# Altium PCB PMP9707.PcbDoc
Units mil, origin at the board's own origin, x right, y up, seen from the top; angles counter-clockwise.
Board outline 2100 x 1500 mil, 2 copper layers (Top Layer, Bottom Layer), stack 62 mil thick; 31 components, 15 nets, 63 pads, 0 vias.
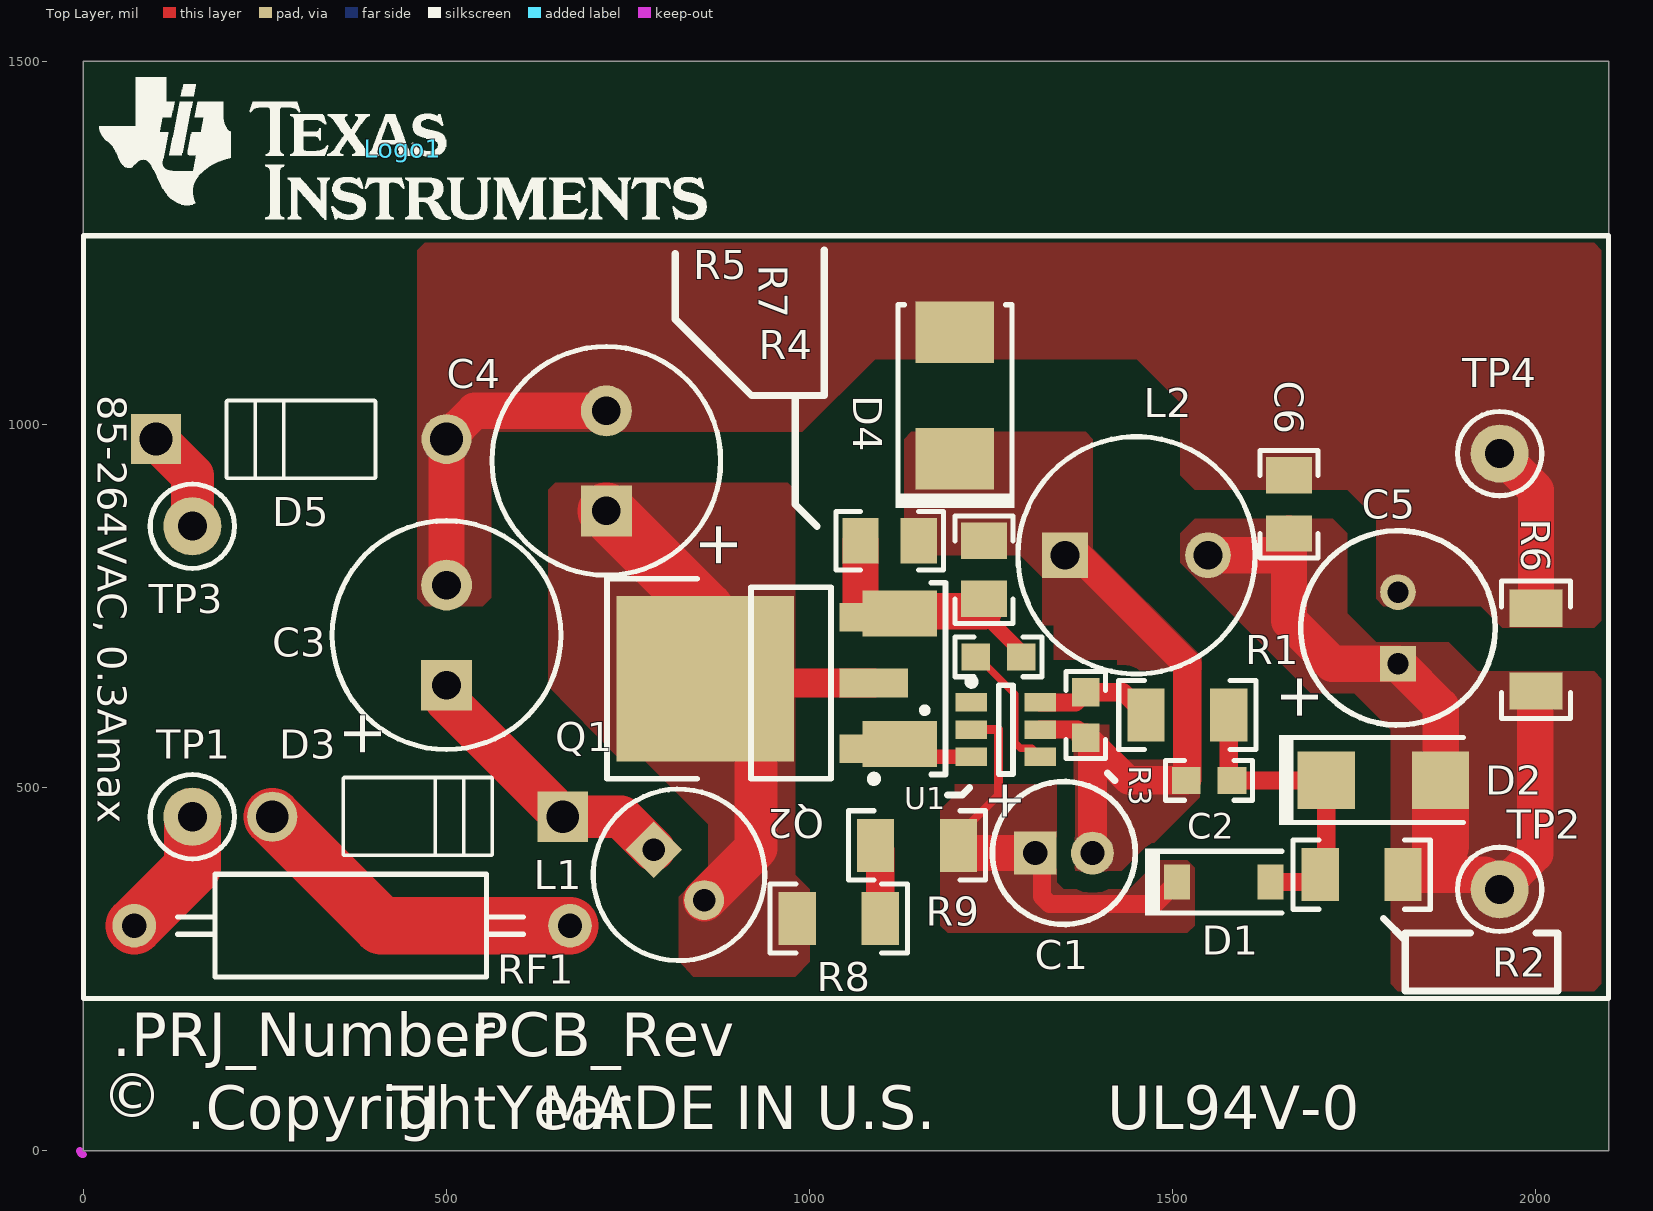
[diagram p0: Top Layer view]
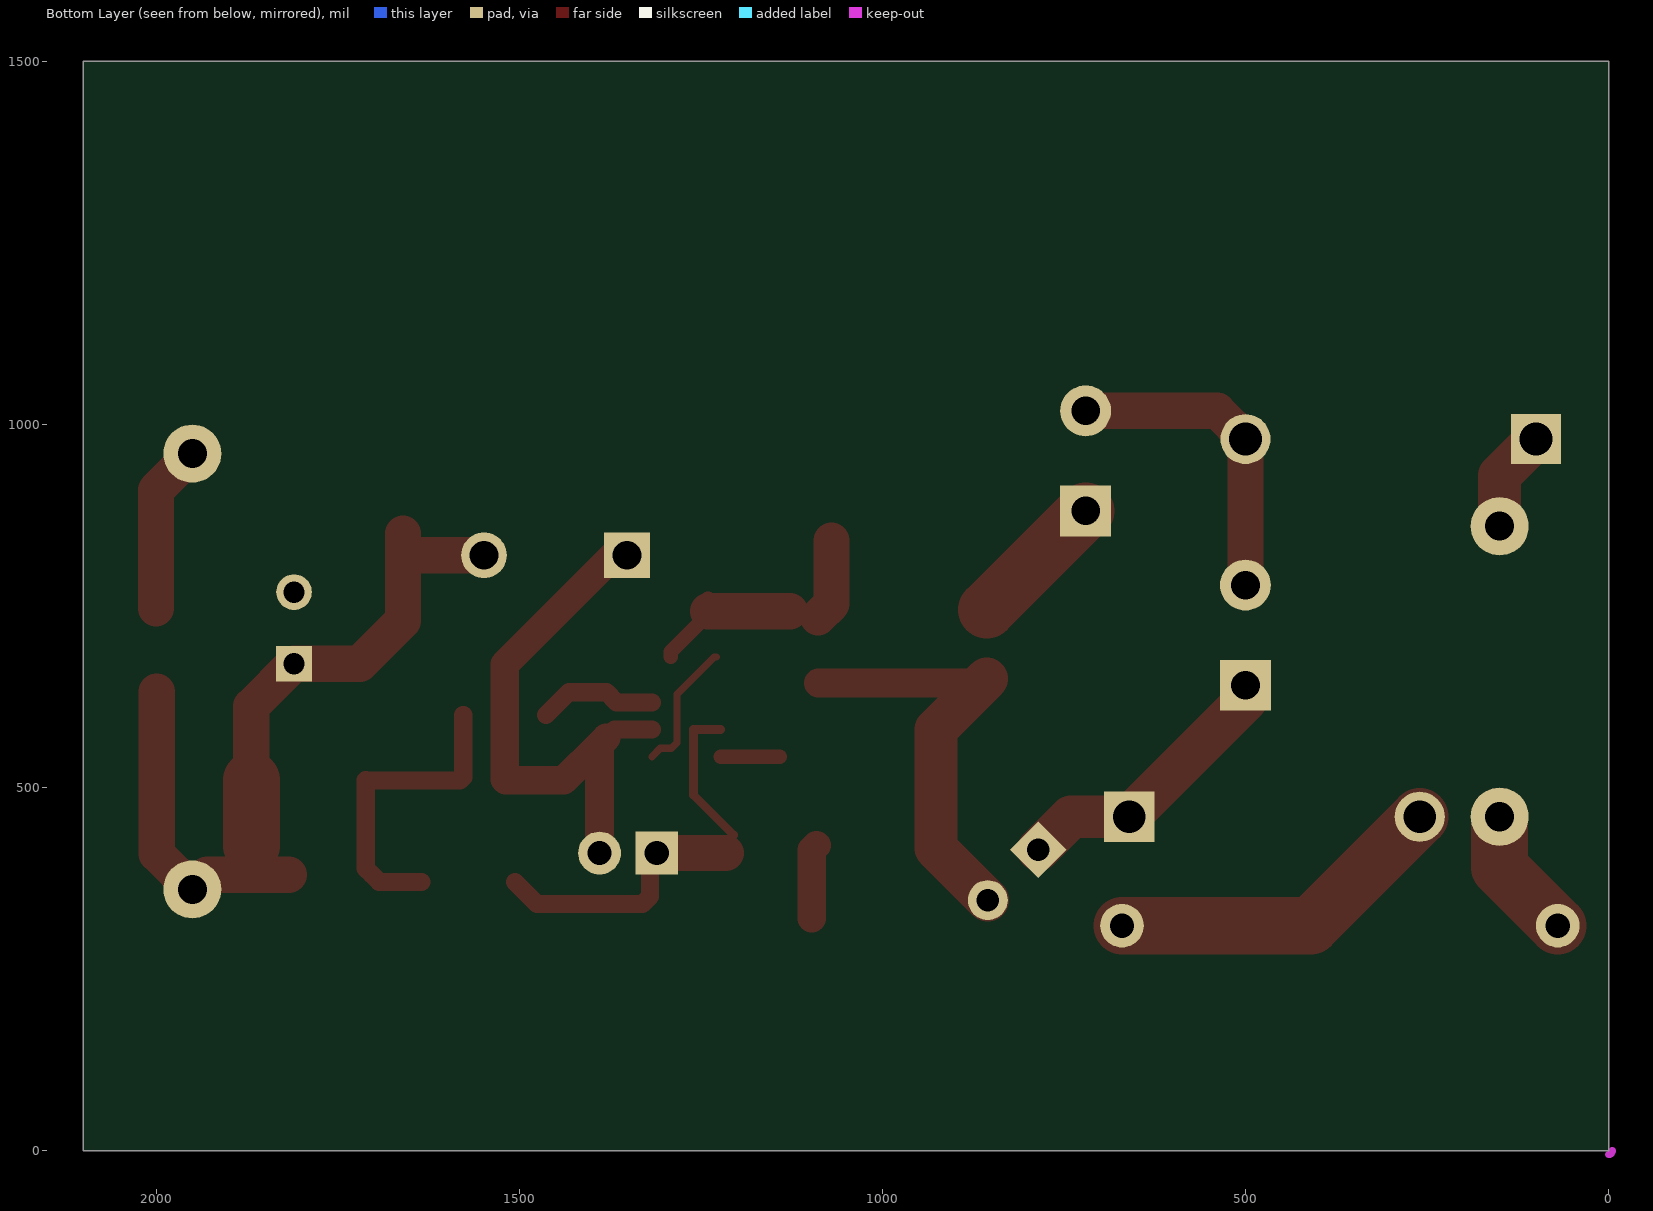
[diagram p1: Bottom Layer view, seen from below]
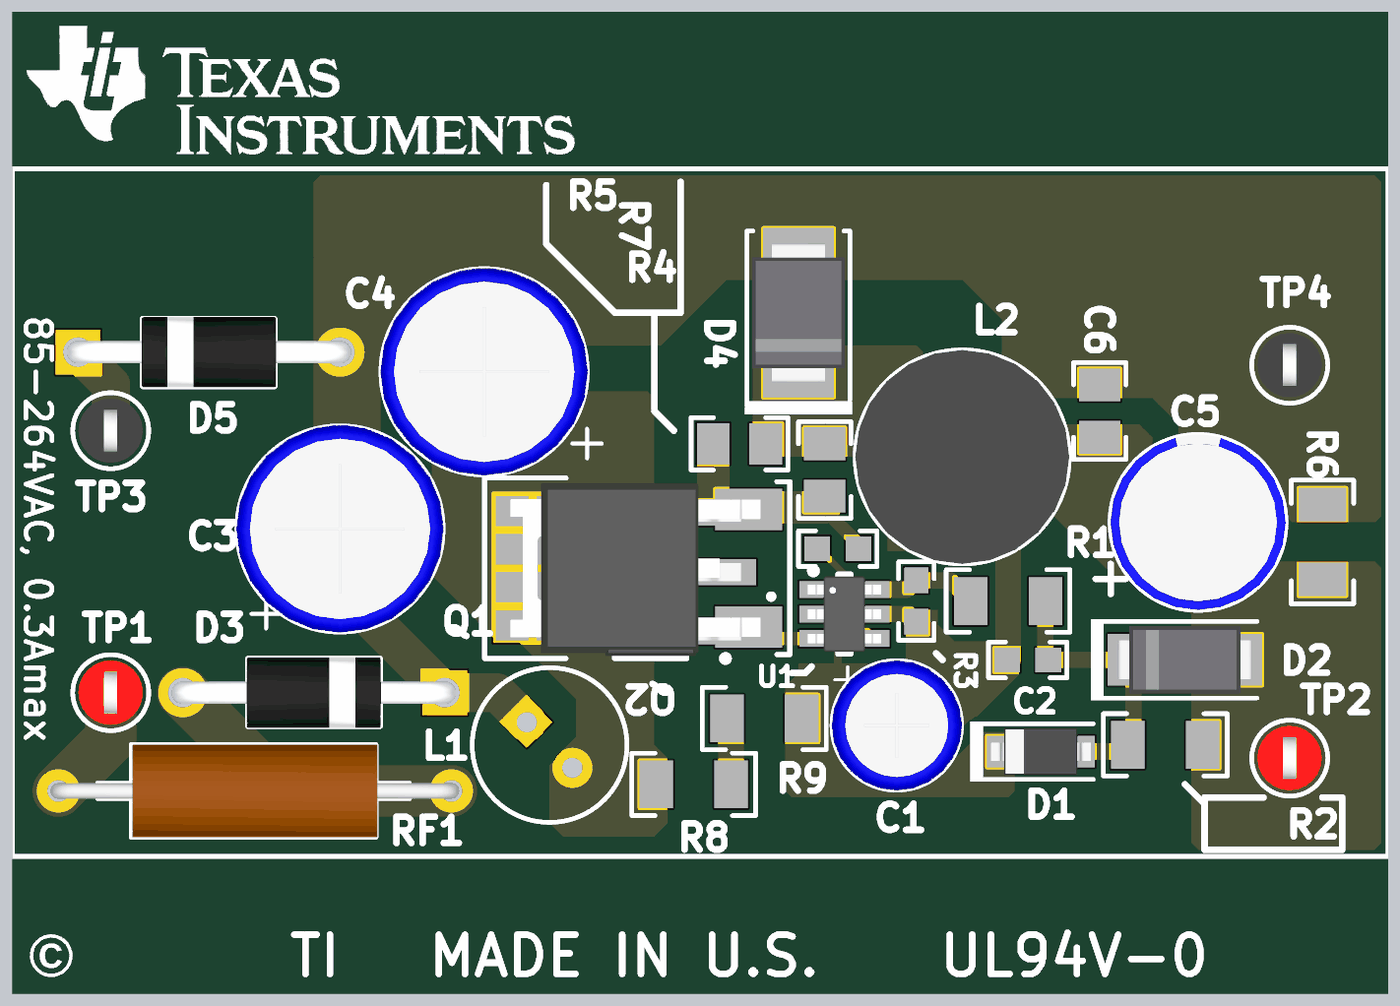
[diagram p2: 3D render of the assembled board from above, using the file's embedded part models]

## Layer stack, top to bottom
Top Layer: signal copper 1.4
Dielectric: core 59.2, FR-4, Dk 4.8
Bottom Layer: signal copper 1.4

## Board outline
0,0 2100,0 2100,1500 0,1500

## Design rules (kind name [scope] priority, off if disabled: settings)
AcuteAngle [All] p1: minimum=4.50000000000000E+0001 checktracksonly=FALSE
AssemblyTestPointUsage [All] p1: valid=2
Clearance Clearance_BoardEdge_MountingHoles [OnCopper and InComponentClass('Mounting Holes') vs IsKeepOut] p1: gap=40
Clearance Clearance_BoardEdge_Poly [OnCopper and InPoly vs IsKeepOut] p2: gap=25
Clearance Clearance_BoardEdge [OnCopper and Not InComponentClass('Logo') and not InComponentClass('FiducialMark') and not InRegion(1000,500,4000,800) and Not IsKeepout vs IsKeepOut] p3: gap=75
Clearance Clearance_Poly [InPolygon] p4: gap=25
Clearance [All] p5: gap=8
ComponentClearance ComponentClearance_Logo [InComponentClass(Logo)] p1: gap=50 collisioncheckmode=3 verticalgap=10 showdistances=FALSE
ComponentClearance ComponentClearance_ScrewToNut [(HasFootprint('NY PMS 440 0025 PH')) vs (HasFootprint('Keystone_1902C'))] p2: gap=5 collisioncheckmode=3 verticalgap=10 showdistances=FALSE
ComponentClearance ComponentClearance_MountingHoles [InComponentClass('Mounting Holes')] p3: gap=2 collisioncheckmode=3 verticalgap=100000 showdistances=FALSE
ComponentClearance ComponentClearance_SmallPassives [HasFootprint('0201*') or HasFootprint('0402*') or HasFootprint('0508') or HasFootprint('0603*') or HasFootprint('0612') or HasFootprint('0805*') or HasFootprint('0815*') or HasFootprint('0830*') or HasFootprint('1206*') or HasFootprint('1210*') or HasFootprint('1808*') or HasFootprint('1812*') or HasFootprint('1825*') or HasFootprint('2010*') or HasFootprint('2220*') or HasFootprint('2225*') or HasFootprint('2512*') or HasFootprint('2728*') or HasFootprint('3518*') vs HasFootprint('0201*') or HasFootprint('0402*') or HasFootprint('0508') or HasFootprint('0603*') or HasFootprint('0612') or HasFootprint('0805*') or HasFootprint('0815*') or HasFootprint('0830*') or HasFootprint('1206*') or HasFootprint('1210*') or HasFootprint('1808*') or HasFootprint('1812*') or HasFootprint('1825*') or HasFootprint('2010*') or HasFootprint('2220*') or HasFootprint('2225*') or HasFootprint('2512*') or HasFootprint('2728*') or HasFootprint('3518*')] p4: gap=10 collisioncheckmode=3 verticalgap=10 showdistances=FALSE
ComponentClearance ComponentClearance_THtoSMT [IsThruComponent vs IsSMTComponent] p5: gap=10 collisioncheckmode=3 verticalgap=10 showdistances=FALSE
ComponentClearance ComponentClearance_THtoTH [IsThruComponent vs IsThruComponent] p6: gap=10 collisioncheckmode=3 verticalgap=10 showdistances=FALSE
ComponentClearance [All] p7: gap=10 collisioncheckmode=3 verticalgap=10 showdistances=FALSE
DiffPairsRouting [All] p1: maxlimit=100 minlimit=10 mostfreqgap=10 maxuncoupledlength=1000
FabricationTestPointUsage TestPointUsage [All] p1: valid=2 allowmultiple=FALSE
FabricationTestpoint Testpoint [All] p1: side=3 testpointundercomponent=TRUE minsize=40 maxsize=100 preferedsize=60 minholesize=0 maxholesize=40 preferedholesize=32 testpointgrid=1 allowsidetop=TRUE allowsidebottom=TRUE usegrid=TRUE gridtolerance=0.01
FanoutControl Fanout_LCC [IsLCC] p1: bgadir=Out bgaviamode=Centered fanoutstyle=Auto fanoutdirection=Alternating viagrid=1 // Fanout_LCC (Default Rule)
FanoutControl Fanout_BGA [IsBGA] p2: bgadir=Out bgaviamode=Centered fanoutstyle=Auto fanoutdirection=Alternating viagrid=1 // Fanout_BGA (Default Rule)
FanoutControl Fanout_Default [All] p4: bgadir=Out bgaviamode=Centered fanoutstyle=Auto fanoutdirection=Alternating viagrid=1 // Fanout_Default (Default Rule)
FanoutControl Fanout_Small [(CompPinCount < 5)] p5: bgadir=Out bgaviamode=Centered fanoutstyle=Auto fanoutdirection=OutThenIn viagrid=1 // Fanout_Small (Default Rule)
HoleSize [All] p1: absolutevalues=TRUE maxlimit=251 minlimit=8 maxpercent=80.000 minpercent=20.000
MinimumAnnularRing [All] p1: minimumring=9
MinimumSolderMaskSliver MinimumSolderMaskSliver_Logo [InComponentClass('Logo') vs InComponentClass('Logo')] p1: minsoldermaskwidth=0.7
MinimumSolderMaskSliver [All] p2: minsoldermaskwidth=4
PlaneConnect [All] p1: planeconnectstyle=Relief reliefexpansion=10 reliefentries=4 reliefconductorwidth=10 reliefairgap=10
PolygonConnect PolygonConnect_6 [All vs IsNamedPolygon('GND_T') Or  IsNamedPolygon('C5_1_T') Or  IsNamedPolygon('C1_2_T') Or  IsNamedPolygon('C1_1_T') Or  IsNamedPolygon('C4_1')] p1: connectstyle=Direct reliefconductorwidth=10 reliefentries=4 polygonreliefangle="90 Angle" airgapwidth=10
PolygonConnect PolygonConnect_5 [All vs IsNamedPolygon('C4_1') Or  IsNamedPolygon('C5_1_T')] p2: connectstyle=Direct reliefconductorwidth=10 reliefentries=4 polygonreliefangle="90 Angle" airgapwidth=10
PolygonConnect PolygonConnect_4 [All vs IsNamedPolygon('C1_2') Or  IsNamedPolygon('C4_1') Or  IsNamedPolygon('C5_1') Or  IsNamedPolygon('GND')] p3: connectstyle=Direct reliefconductorwidth=10 reliefentries=4 polygonreliefangle="90 Angle" airgapwidth=10
PolygonConnect PolygonConnect_3 [All vs IsNamedPolygon('C4_1') Or  IsNamedPolygon('GND') Or  IsNamedPolygon('C5_1')] p4: connectstyle=Direct reliefconductorwidth=10 reliefentries=4 polygonreliefangle="90 Angle" airgapwidth=10
PolygonConnect PolygonConnect_2 [All vs IsNamedPolygon('C5_1')] p5: connectstyle=Direct reliefconductorwidth=10 reliefentries=4 polygonreliefangle="90 Angle" airgapwidth=10
PolygonConnect PolygonConnect_1 [All vs IsNamedPolygon('C1_2_T') Or  IsNamedPolygon('C4_1_T') Or  IsNamedPolygon('GND_T')] p6: connectstyle=Direct reliefconductorwidth=10 reliefentries=4 polygonreliefangle="90 Angle" airgapwidth=10
PolygonConnect [All] p7: connectstyle=Relief reliefconductorwidth=10 reliefentries=4 polygonreliefangle="90 Angle" airgapwidth=10
RoutingVias [All] p1: holewidth=16 width=34 viastyle="Through Hole" minholewidth=8 minwidth=26 maxholewidth=40 maxwidth=65
SMDToCorner [All] p1: distance=30000
SilkToSilkClearance [All] p1: silktosilkclearance=5
SilkscreenOverComponentPads [All] p1: minsilkscreentomaskgap=5
SolderMaskExpansion [All] p1: expansion=3
Width [All] p1: maxlimit=100 minlimit=6 preferedwidth=10 checkconnectedcopper=TRUE
14 further rules are at their usual default settings.

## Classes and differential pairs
component class Logo: Logo1

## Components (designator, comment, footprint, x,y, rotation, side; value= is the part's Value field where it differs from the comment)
C1 "UVR1V100MDD1TA" CAPPR2-5x11 1350,410 r0 top
C2 "06035A220JAT2A" 0603 1550,510 r180 top
C3 "400AX6R8M8x11" CAPPRD350W60D800H1100 500,710 r90 top
C4 "400AX6R8M8x11" CAPPRD350W60D800H1100 720,950 r90 top
C5 "EEU-FR1E151B" CAPPR250W50D630H1120 1810,720 r90 top
C6 "08055C105KAT2A" 0805_HV 1660,890 r90 top
D1 "1N4148W-7-F" SOD-123 1570,370 r0 top
D2 "ES1J-TP" SMA 1790,510.32 r0 top
D3 "1N4007" DO-41 460,460 r180 top
D4 "MURS160-13-F" SMB 1200,1040 r90 top
D5 "1N4007" DO-41 300,980 r0 top
L1 "7447462102" IND_WE-TI_XS 820,380 r315 top
L2 "744772221" IND_WE-TI_8095 1450,820 r0 top
Logo1 "Texas Instruments" TI_Stacked_Overlay_Small 440,1380 r0 top
Q1 "FJD5304DTF" DPAK 990,650 r180 top
Q2 "STN2580" SOT-223 974.25,644.09 r180 top
R1 "CRCW120638K3FKEA" 1206 1520,600 r0 top
R2 "CRCW1206475KFKEA" 1206 1760,380.32 r180 top
R3 "CRCW060317K8FKEA" 0603 1380,600 r90 top
R4 "CRCW0603511RFKEA" 0603 1260,680 r180 top
R5 "CRCW08051R20JNEA" 0805_HV 1110,840 r0 top
R6 "CRCW120612K0JNEA" 1206 2000,690 r270 top
R7 "CRCW08051R20JNEA" 0805_HV 1240,800 r90 top
R8 "CRCW12063M30JNEA" 1206 1040,320 r0 top
R9 "CRCW12063M30JNEA" 1206 1147.75,420.61 r0 top
RF1 "FKN1WSJR-52-4R7" RESAD1524W55L900D150 370,310 r180 top
TP1 "5000" Keystone5000 150,460 r0 top
TP2 "5000" Keystone5000 1950,360 r0 top
TP3 "5001" Keystone5001 150,860 r0 top
TP4 "5001" Keystone5001 1950,960 r0 top
U1 "UCC28722DBV" DBV0006A_N 1270,580 r0 top

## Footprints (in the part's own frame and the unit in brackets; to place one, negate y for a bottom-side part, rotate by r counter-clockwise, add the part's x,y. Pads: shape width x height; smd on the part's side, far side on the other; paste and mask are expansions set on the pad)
0603 [mm] "0603 from SM-752 data"
  rect 1x0.95 smd: 1(-0.8,0) 2(0.8,0)
  silkscreen extent -1.52,-0.69 1.52,0.69, body extent -0.87,-0.47 0.87,0.47, height 0.85
0805_HV [mil] "0805 with 30mil clearance between pads"
  rect 50x63 smd: 1(-40,0) 2(40,0)
  silkscreen extent -74,-40 74,40, body extent -43,-29 43,29, height 43
1206 [mm] "1206 from SM-752 data"
  rect 1.3x1.85 smd: 1(-1.45,0) 2(1.45,0)
  silkscreen extent -2.4,-1.21 2.4,1.21, body extent -1.7,-0.9 1.7,0.9, height 1.35
CAPPR2-5x11 [mm] "Capacitor, Electrolytic, Radial; Body 5 x 11 mm (Dia.xH typ); Pin Spacing 2 mm (typ)"
  rect 1.5x1.5 hole 0.85: 1(-1,0)
  round 1.5 hole 0.85: 2(1,0)
  silkscreen extent -2.5,-2.5 2.5,2.5, body extent -2.53,-2.53 2.53,2.52, height 11.29
CAPPR250W50D630H1120 [mm] "PANASONIC"
  rect 1.25x1.25 hole 0.75: 1(-1.25,0)
  round 1.25 hole 0.75: 2(1.25,0)
  silkscreen extent -3.4,-3.4 3.4,3.4, body extent -3.37,-3.39 3.4,3.39, height 12.21
CAPPRD350W60D800H1100 [mm] "Capacitor, Alum, 8x11mm"
  rect 1.78x1.78 hole 1: 1(-1.75,0)
  round 1.78 hole 1: 2(1.75,0)
  silkscreen extent -4,-4 4,4, body extent -4.03,-4.03 4.03,4.02, height 11.79
DBV0006A_N [mm] "SOT23, 6-Leads, Body 2.9x1.6mm, Pitch 0.95mm, Lead Span 2.8mm, IPC Medium Density"
  rect 1.1x0.65 smd: 1(-1.2,0.95) 2(-1.2,0) 3(-1.2,-0.95) 4(1.2,-0.95) 5(1.2,0) 6(1.2,0.95)
  silkscreen extent -1.32,-1.55 0.25,1.8, body extent -1.42,-1.46 1.42,1.46, height 1.11
DO-41 [mm] "diode"
  rect 1.75x1.75 hole 1.15: 1(-5.08,0)
  round 1.75 hole 1.15: 2(5.08,0)
  silkscreen extent -2.62,-1.37 2.59,1.35, body extent -5.51,-1.36 5.51,1.36, height 2.72
DPAK [mm] "D-PAK, 3-Pads, Body 6.22x6.73mm (max), TO-252AA using nominal STEP model"
  rect 2.6x1.6 smd: 1(-3.4,2.28) 3(-3.4,-2.28)
  rect 6.2x5.8 smd paste-2.9: 4(3.4,0)
  silkscreen extent -5,-3.5 6.83,3.5, body extent -3.86,-3.29 5.84,3.29, height 2.48
IND_WE-TI_8095 [mm] "Wurth WE-TI 8095"
  rect 1.6x1.6 hole 1: 1(-2.5,0)
  round 1.6 hole 1: 2(2.5,0)
  silkscreen extent -4.15,-4.15 4.15,4.15, body extent -4.12,-4.14 4.15,4.14, height 10
IND_WE-TI_XS [mm] "Wurth WE-TI 5075"
  rect 1.4x1.4 hole 0.787: 1(-1.25,0)
  round 1.4 hole 0.787: 2(1.25,0)
  silkscreen extent -3,-3 3,3, body extent -3.01,-3.01 3.01,3.01, height 8.5
Keystone5000 [mil] "For Keystone 500x miniature loop terminals"
  round 80 hole 40: 1(0,0)
  silkscreen extent -58,-58 58,58, body extent -49,-49 49,49, height 182
Keystone5001 [mil] "For Keystone 500x miniature loop terminals"
  round 80 hole 40: 1(0,0)
  silkscreen extent -58,-58 58,58, body extent -49,-49 49,49, height 182
RESAD1524W55L900D150 [mil]
  round 60 hole 33.46: 1(-300,0) 2(300,0)
  silkscreen extent -236,-71 240,71, body extent -312,-71 312,71, height 141
SMA [mm] "Molded Diode, 2-Leads, Body 4.3x2.6mm, IPC Medium Density, based on OnSemi component dimensions and land pattern"
  rect 2x2 smd: 1(-2,0) 2(2,0)
  silkscreen extent -3.66,-1.57 2.79,1.57, body extent -2.6,-1.3 2.6,1.3, height 2.42
SMB [mil] "Molded Diode, 2-Leads, Body 5.4x3.6mm, IPC Medium Density, based on OnSemi component dimensions"
  rect 85x107.99 smd: 1(-87.01,0) 2(87.01,0)
  silkscreen extent -155,-82 125,82, body extent -106,-71 106,71, height 91
SOD-123 [mm] "On Semi recommended land pattern"
  rect 0.915x1.22 smd: 1(-1.637,0) 2(1.637,0)
  silkscreen extent -2.74,-1.17 2.03,1.17, body extent -1.93,-0.9 1.93,0.9, height 1.35
SOT-223 [mm] "SOT223/SC73, 4-Leads, Body 6.5x3.5mm, Pitch 2.3mm, Lead Span 7mm, IPC Medium Density"
  rect 2.4x1 smd: 1(-2.9,2.3) 2(-2.9,0) 3(-2.9,-2.3)
  rect 2.4x3.3 smd: 4(2.9,0)
  silkscreen extent -3.03,-3.35 1.4,3.47, body extent -3.5,-3.25 3.5,3.25, height 1.62
TI_Stacked_Overlay_Small [mil]
  silkscreen extent -418,-98 418,98

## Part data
C1: "CAP, AL, 10uF, 35V, +/-20%, TH"
C2: "CAP, CERM, 22pF, 50V, +/-5%, C0G/NP0, 0603"
C3 C4: "CAP, AL, 6.8uF, 400V, +/-20%, TH"
C5: library part EEU-EB1E101S, "CAP ALUM 150UF 25V 20% RADIAL"
C6: "CAP, CERM, 1uF, 50V, +/-10%, X7R, 0805"
D1: "Diode, Ultrafast, 100V, 0.15A, SOD-123"
D2: library part ES1D-13-F, "DIODE FAST REC 600V 1A DO214AC"
D3 D5: "Diode, P-N, 1000V, 1A, TH"
D4: "Diode, Ultrafast, 600V, 1A, SMB"
L1: "Inductor, Unshielded Drum Core, Ferrite, 1mH, 0.25A, 4.38 ohm, TH"
L2: library part 744772100, "INDUCTOR 220UH .64A 8095 RAD"
Logo1: library part TI_Logo, "Texas Instrument Corporate Signature"
Q1: library part "2SD1760TLR, Rohm", "TRANS SWITCHING FAST HV DPAK"
Q2: library part "DZTA42-13, Diodes Inc.", "MOSF NPN 400V 1A SOT-223"
R1: "RES, 38.3k ohm, 1%, 0.25W, 1206"
R2: "RES, 475k ohm, 1%, 0.25W, 1206"
R3: "RES, 17.8k ohm, 1%, 0.1W, 0603"
R4: "RES, 511 ohm, 1%, 0.1W, 0603"
R5 R7: "RES, 1.2 ohm, 5%, 0.125W, 0805"
R6: "RES, 12k ohm, 5%, 0.25W, 1206"
R8 R9: "RES, 3.3Meg ohm, 5%, 0.25W, 1206"
RF1: "RES, 4.7 ohm, 5%, 1W, Fusible, TH"
TP1 TP2: "Test Point, Miniature, Red, TH"
TP3 TP4: "Test Point, TH, Miniature, Black"
U1: "Constant-Voltage, Constant-Current Controller With Primary-Side Regulation, BJT Drive, DBV0006A"

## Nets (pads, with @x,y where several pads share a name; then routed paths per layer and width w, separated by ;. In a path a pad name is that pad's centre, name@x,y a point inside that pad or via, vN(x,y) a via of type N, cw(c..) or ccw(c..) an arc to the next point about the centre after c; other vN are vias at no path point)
GND: C3.2 C4.2 C5.2 C6.2 D4.2 D5.2 R6.1 TP4.1 | length 670.8
  Top Layer w50: C3.2 D5.2 538.9,1018.9 C4.2 ; TP4.1 2000,910 R6.1
NetC1_1: C1.1 D1.1 R9.2 U1.2 | length 553.2
  Top Layer w12: R9.2@1204.84,434.84 1260,490 1260,580 U1.2
  Top Layer w25: C1.1@1320,400.63 1320,350 1330,340 1475.53,340 D1.1
  Top Layer w50: R9.2@1215.45,410 C1.1
NetC1_2: C1.2 C2.2 D4.1 L2.1 R3.1 R5.2 R7.2 U1.5 | length 752.1
  Top Layer w25: U1.5 1368.5,580 R3.1
  Top Layer w39.37: L2.1@1370,820 1520,670 1520,511.5 C2.2 1438.5,510 R3.1@1389.37,559.13 ; R3.1 R3.1@1389.37,559.13 ; C1.2 R3.1@1389.37,559.13
NetC2_1: C2.1 D1.2 D2.1 R1.2 R2.2 | length 427.5
  Top Layer w25: R1.2 1577.09,514.41 C2.1 D2.1@1710.94,510 ; D1.2 1692.6,370 R2.2 1711.26,388.66 D2.1
NetC3_1: C3.1 D3.1 L1.1 | length 391.3
  Top Layer w59.06: C3.1 500,620 D3.1 740,460 L1.1
NetC4_1: C4.1 L1.2 Q1.4 Q2.2 Q2.4 R8.1 | length 782.3
  Top Layer w39.37: Q2.4@862.05,644.09 Q2.2
  Top Layer w59.06: L1.2 926.2,416.6 926.2,579.94 862.05,644.09 Q1.4
  Top Layer w78.74: C4.1 Q1.4@856.14,744.96
NetC5_1: C5.1 C6.1 D2.2 L2.2 R2.1 R6.2 TP2.1 | length 1113
  Top Layer w50: L2.2 1656,820 ; C6.1 1660,730 1719.21,670.79 C5.1 1868.74,612.05 D2.2 ; R2.1 TP2.1@1929.68,380.32 ; 1868.74,389.06 1868.74,420 ; TP2.1 1999.04,409.04 R6.2@1999.04,631.95
  Top Layer w78.74: 1868.74,420 D2.2
NetD3_2: D3.2 RF1.1 | length 472.1
  Top Layer w78.74: D3.2 410,310 RF1.1
NetD5_1: D5.1 TP3.1 | length 140.7
  Top Layer w59.06: D5.1 150,930 TP3.1
NetQ1_1: Q1.1 Q2.1 U1.3 | length 81.3
  Top Layer w20: Q1.1@1141.5,542.6 U1.3
NetQ1_3: Q1.3 Q2.3 R4.1 R5.1 R7.1 | length 327.3
  Top Layer w20: R7.1 1250,750 1250,728.54 1291.5,687.05 R4.1
  Top Layer w50: R5.1 1070,753.07 Q2.3 ; Q2.3@1127.01,742.91 R7.1@1240,742.91
NetR1_1: R1.1 R3.2 U1.6 | length 164.6
  Top Layer w25: U1.6 1365.91,617.4 R3.2 1431.42,631.5 R1.1
NetR4_2: R4.2 U1.4 | length 184.8
  Top Layer w10: R4.2 1231.3,680 1282.59,628.71 1282.59,561.82 1290.21,554.2 1305.64,554.2 U1.4
NetR8_2: R8.2 R9.1 | length 103.3
  Top Layer w39.37: R9.1 1097.09,414.19 R8.2
NetRF1_2: RF1.2 TP1.1 | length 183.1
  Top Layer w78.74: RF1.2 150,390 TP1.1
pads on no net: U1.1

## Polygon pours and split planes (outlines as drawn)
NetC1_2 on Top Layer "C1_2_T" (solid, pour order 13): 1301.48,572.05 1303.53,570 1350,570 1360,560 1352.73,552.73 1352.73,550 1360,550 1360,390 1370,380 1430,380 1540,490 1540,680 1390,830 1390,980 1380,990 1140,990 1130,980 1130,830 1140,820 1290,820 1320,790 1320,650 1301.48,630
NetC1_1 on Top Layer "C1_1_T" (solid, pour order 11): 1520,400 1530,390 1530,380 1530,310 1520,300 1500,300 1190,300 1180,310 1180,340 1180,466.87 1180,470 1190,480 1200,490 1200,580 1210,590 1230,590 1280,590 1340,530 1340,500 1340,370 1350,360 1380,360 1420,360 1440,360 1480,400
NetC4_1 on Top Layer "C4_1" (solid, pour order 7): 820,261.54 840,240 980,240 1000,260 1000,360 980,380 980,910 970,920 650,920 640,910 640,640 738.03,539.76 738.27,540 770,540 860,450 860,390 820,350
NetC5_1 on Top Layer "C5_1_T" (solid, pour order 5): 1800,230 1810,220 2080,220 2090,230 2090,650 2080,660 1920,660 1880,700 1780,700 1740,740 1740,850 1720,870 1530,870 1510,850 1510,810 1690,630 1750,630 1800,580
GND on Top Layer "GND_T" (solid, pour order 8): 1923.74,750 1953.74,720 2080,720 2090,730 2090,1240 2080,1250 470,1250 460,1240 460,760 470,750 550,750 561.59,761.59 561.59,981.59 570,990 990,990 1090,1090 1450,1090 1510,1030 1510,930 1530,910 1740,910 1780,870 1780,760 1790,750

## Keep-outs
Keep-Out Layer:
  lines w10: -5,0 ccw(c0,0) 0,-5 ; -5,0 ccw(c0,0) 0,-5 ; -5,0 ccw(c0,0) 0,-5 ; -5,0 ccw(c0,0) 0,-5 ; -5,0 ccw(c0,0) 0,-5 ; -5,0 ccw(c0,0) 0,-5
  text ".Layer_Name" at 577,-858.49 h60

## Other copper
Top Layer:
  text ".Layer_Name" at 577,-858.49 h60
Bottom Layer:
  text ".Layer_Name" at 577,-858.49 h60

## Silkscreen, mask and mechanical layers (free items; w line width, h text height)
Top Overlay:
  lines w7: 0,210 0,1260 2100,1260 2100,210 0,210
  lines w10: 815,1235 815,1145 920,1040 1020,1040 1020,1240 ; 980,1040 980,890 1010,860 ; 1190,490 1210,490 1220,500 ; 1410,520 1420,510 ; 1790,320 1820,290 1820,280 ; 1910,300 1820,300 1820,220 2030,220 2030,300 2000,300
  text "85-264VAC, 0.3Amax" at 20,1040 h40 r270
  text ".PRJ_Number" at 40,130 h60
  text ".PCB_Rev" at 510,130 h60
  text ".CopyrightYear" at 142,30 h60
  text "TI" at 418,30 h60
  text "MADE IN U.S." at 630,30 h60
  text "UL94V-0" at 1410,30 h60
  text "©" at 25,26.48 h105
  text ".Layer_Name" at 577,-858.49 h60
Bottom Overlay:
  text ".Layer_Name" at 577,-858.49 h60
Top Paste:
  text ".Layer_Name" at 577,-858.49 h60
Bottom Paste:
  text ".Layer_Name" at 577,-858.49 h60
Top Solder:
  text ".Layer_Name" at 577,-858.49 h60
  text ".Layer_Name" at 577,-858.49 h60
Bottom Solder:
  text ".Layer_Name" at 577,-858.49 h60
Drill Guide:
  text ".Layer_Name" at 577,-858.49 h60
M1 Board Outline:
  the board outline again, w10
  text ".Layer_Name" at 577,-858.49 h60
M2 Board Dimensions:
  rectangle: 124.5,-410.5 499.5,-285.5
  rectangle: -0.5,-285.5 124.5,-160.5
  lines w7: -0.5,-285.5 999.5,-285.5 ; 124.5,-410.5 124.5,-160.5 ; 249.5,-410.5 249.5,-160.5 ; 499.5,-410.5 499.5,-160.5 ; 749.5,-410.5 749.5,-160.5 ; -0.5,-410.5 -0.5,-160.5 999.5,-160.5 999.5,-410.5 -0.5,-410.5
  lines w10: -0.5,-475.5 -0.5,-455.5 ; 59.5,-485.5 -0.5,-465.5 ; 59.5,-445.5 -0.5,-465.5 ; 243.58,-465.5 -0.5,-465.5 ; 755.42,-465.5 999.5,-465.5 ; 939.5,-485.5 999.5,-465.5 ; 939.5,-445.5 999.5,-465.5 ; 999.5,-475.5 999.5,-455.5
  text "25.4 (mm)" at 253.58,-501.49 h60
  text ".Layer_Name" at 577,-858.49 h60
M3 3D STEP Top:
  text ".Layer_Name" at 577,-858.49 h60
M4 3D STEP Bottom:
  text ".Layer_Name" at 577,-858.49 h60
M5 Assembly Top:
  lines w7: 5139,110.5 6264,110.5 ; 5139,233 6261.5,233 ; 5454,-9.5 5454,353 ; 5839,-9.5 5139,-9.5 ; 5839,353 5139,353 ; 5139,-9.5 5139,353 ; 5139,-9.5 6264,-9.5 6264,353 5139,353
  lines w10: -292,-930.17 6308,-930.17 ; -292,-726.83 6310,-726.83 ; -292,-523.5 -292,-1133.5 3713,-1133.5 6310,-1133.5 6310,-523.5 -291.5,-523.5 -291.5,-1133.5 1284,-1133.5 ; 2173,-1133.5 2173,-523.5 ; 3440,-726.83 3440,-523.5 ; 4280,-726.83 4280,-523.5 ; 4902,-1140 4902,-937.17
  text "TABLE 1" at 5526.5,388 h40
  text "Variant" at 5164,278 h40
  text "Label text" at 5599,278 h40
  text "001" at 5231.5,158 h40
  text "ChangeMe!" at 5509,155.5 h40
  text "002" at 5231.5,33 h40
  text "ChangeMe!" at 5504,30.5 h40
  text "COMPONENTS MARKED 'DNP' SHOULD NOT BE POPULATED." at 1153.5,-318.5 h60
  text "ASSEMBLY VARIANT:" at 1153,-434 h60
  text ".VariantName" at 2189,-434 h60
  text "PCB VIEWED FROM TOP SIDE" at -228.5,-655.67 h60
  text "BOARD #:" at 2248,-655.67 h60
  text ".PRJ_Number" at 2793.5,-655.67 h60
  text "REV:" at 3638,-655.67 h60
  text ".PCB_Rev" at 3929.5,-655.67 h60
  text "SVN REV:" at 4476,-655.67 h60
  text ".VersionControl_RevNumber" at 4982,-655.67 h60
  text "IGNORE ->" at -228.5,-858.49 h60
  text "PLOT NAME =" at -228.5,-1064.34 h60
  text ".plot_File_Name" at 577,-1064.34 h60
  text "GENERATED    :" at 2250,-1064.34 h60
  text ".Print_Date" at 3119.5,-1064.34 h60
  text ".Print_Time" at 3848.5,-1064.34 h60
  text "TEXAS INSTRUMENTS" at 5113,-1064.34 h60
M6 Assembly Bottom:
  lines w10: -292.5,-727.33 6309.5,-727.33 ; -290.5,-930.67 6309.5,-930.67 ; 1115.5,-1140.5 1115.5,-937.67 ; 1737.5,-727.33 1737.5,-524 ; 2577.5,-727.33 2577.5,-524 ; 3844.5,-1134 3844.5,-524 ; 4733.5,-1134 6309,-1134 6309,-524 -292.5,-524 -292.5,-1134 2304.5,-1134 6309.5,-1134 6309.5,-524
  text "COMPONENTS MARKED 'DNP' SHOULD NOT BE POPULATED." at 6102,-318 h60
  text ".VariantName" at 5058,-434 h60
  text "ASSEMBLY VARIANT:" at 6097,-434 h60
  text ".VersionControl_RevNumber" at 1035.5,-656.17 h60
  text "SVN REV:" at 1541.5,-656.17 h60
  text ".PCB_Rev" at 2088,-656.17 h60
  text "REV:" at 2379.5,-656.17 h60
  text ".PRJ_Number" at 3224,-656.17 h60
  text "BOARD #:" at 3769.5,-656.17 h60
  text "PCB VIEWED FROM BOTTOM SIDE" at 6246,-656.17 h60
  text "IGNORE ->" at 2547.85,-858.49 h60
  text "TEXAS INSTRUMENTS" at 904.5,-1064.84 h60
  text ".Print_Time" at 2169,-1064.84 h60
  text ".Print_Date" at 2898,-1064.84 h60
  text "GENERATED    :" at 3767.5,-1064.84 h60
  text ".plot_File_Name" at 5440.5,-1064.84 h60
  text "PLOT NAME =" at 6246,-1064.84 h60
M9 Title Sheet:
  drawing of 57 lines, arcs and shapes, not listed
  text "1" at 739.84,8036.5 h70
  text "2" at 3235.5,8036.5 h70
  text "3" at 5724.84,8036.5 h70
  text "4" at 8231.51,8036.5 h70
  text "5" at 10730.5,8036.5 h70
  text "6" at 13235.5,8036.5 h70
  text "A" at -416.5,6893.5 h70
  text "A" at 14383.5,6893.5 h70
  text "B" at -416.5,4513.5 h70
  text "B" at 14383.5,4513.5 h70
  text "C" at -416.5,2138.5 h70
  text "C" at 14383.5,2138.5 h70
  text "PROJECT TITLE:" at 11343.5,277.5 h45
  text ".PRJ_Title" at 11393.5,144.17 h70
  text "DESIGNED FOR:" at 11343.5,-23.5 h45
  text ".PRJ_Customer" at 11393.5,-163.5 h70
  text "D" at -416.5,-231.5 h70
  text "D" at 14383.5,-231.5 h70
  text "FILE NAME:" at 11343.5,-323.5 h45
  text ".PCB_File_Name_No_Path" at 11393.5,-443.5 h70
  text "Texas Instruments (TI) and/or its licensors do not warrant the accuracy or completeness of this specification" at 6374,-605.34 h45
  text "ENGINEER:" at 11343.5,-613.5 h45
  text "LAYOUT BY:" at 12848.5,-613.5 h45
  text "or any information contained therein. TI and/or its licensors do not warrant that this design will meet" at 6329.01,-718 h45
  text ".PRJ_Engineer" at 11393.5,-768.49 h70
  text ".PCB_Layout" at 12899,-768.49 h70
  text "the specifications, will be suitable for your application or fit for any particular purpose, or will operate in" at 6329.01,-830.67 h45
  text ".Layer_Name" at 577,-858.49 h60
  text "ALTIUM DESIGNER VERSION:" at 12848.5,-923.5 h45
  text "an implementation. TI and/or its licensors do not warrant that the design is production worthy. You should" at 6329.01,-943.33 h45
  text "completely validate and test your design implementation to confirm the system functionality for your application." at 6374,-1056 h45
  text ".print_Scale" at 11393.5,-1056.83 h70
  text ".Application_BuildNumber" at 12899,-1056.83 h70
  text "1" at 739.84,-1263.5 h70
  text "2" at 3235.5,-1263.5 h70
  text "3" at 5724.84,-1263.5 h70
  text "4" at 8231.51,-1263.5 h70
  text "5" at 10730.5,-1263.5 h70
  text "6" at 13235.5,-1263.5 h70
M10 Fab Notes:
  drawing of 212 lines, arcs and shapes, not listed
  text "DESIGN INFORMATION" at 12381.02,6810 h60
  text "(REFER ALSO ARRAY/PANEL PROFILING INFORMATION)" at 12019.46,6648.29 h60
  text "BOARD SIZE" at 11333.46,6644 h60
  text "1500MIL" at 11795.78,6516.18 h60
  text "X" at 12301.46,6516.18 h60
  text "2100MIL" at 12532.78,6516.18 h60
  text "Number of Layers :" at 11736.46,6319 h60
  text "2" at 12831.27,6309 h60
  text "MIN. TRACK WIDTH:" at 11736.46,6180 h60
  text "10" at 12832.7,6180 h60
  text "MIL" at 12987.46,6180 h60
  text "MIN. CLEARANCE:" at 11736.46,6048 h60
  text "10" at 12832.7,6048 h60
  text "MIL" at 12987.46,6048 h60
  text "MIN. VIA PAD SIZE:" at 11736.46,5916 h60
  text "10" at 12802.71,5916 h60
  text "MIL" at 12987.46,5916 h60
  text "0.05mm (2MIL)" at 12431.46,5774.29 h60
  text "MINIMUM ANNULAR RING" at 11407.23,5770 h60
  text "EXTERNAL" at 13139.46,5770 h60
  text "PER" at 11607.23,5652 h60
  text "IPC-D-275 CLASS 2 LEVEL C" at 11827.23,5652 h60
  text "MIL, HOLES" at 13315.46,5539.71 h60
  text "+/-" at 12923,5539 h60
  text "+/-" at 13777,5539 h60
  text "REGISTRATION TOLERANCES:" at 11407.23,5534 h60
  text "METAL" at 12607,5534 h60
  text "5" at 13183.2,5534 h60
  text "3" at 14016.2,5534 h60
  text "MIL" at 14132.46,5534 h60
  text "MATERIAL:" at 11332.46,5324.54 h60
  text "FR-4 High Tg" at 12318.9,5184.21 h60
  text "FR-408" at 11753.46,5175.64 h60
  text "X" at 12165.46,5175.64 h60
  text "OTHER" at 13241.46,5175.64 h60
  text "62 MIL (1.6mm) +/-10%" at 12073.56,5012.92 h60
  text "THICKNESS:" at 11407.23,5008.64 h60
  text "X" at 11945.4,5008.64 h60
  text "OTHER" at 13358.46,5008.64 h60
  text "TOLERANCE:" at 11407.23,4850.64 h60
  text "X" at 12246.53,4850.64 h60
  text "ANSI IPC-6012 TYPE 3 CLASS 2" at 12433.48,4850.64 h60
  text "OTHER +/-" at 12433.46,4694.64 h60
  text "BOW & TWIST:" at 11407.23,4537.64 h60
  text "X" at 12246.53,4537.64 h60
  text "ANSI IPC-6012 TYPE 3 CLASS 2" at 12433.48,4537.64 h60
  text "OTHER +/-" at 12433.46,4379.13 h60
  text "COPPER THICKNESS (FINISHED):" at 11332.46,4243.64 h60
  text "1.4MIL (1oz)" at 12212.46,4090.92 h60
  text "2MIL (1.4oz)" at 12979.46,4090.92 h60
  text "2.8MIL (2oz)" at 13706.46,4090.92 h60
  text "OUTER:" at 11689.46,4086.64 h60
  text "X" at 12084,4086 h60
  text "X" at 13580,3940 h60
  text "1.4MIL (1oz)" at 12212.46,3933.92 h60
  text "2.8MIL (2oz)" at 12979.46,3933.92 h60
  text "N/A" at 13706,3934.29 h60
  text "INNER SIGNAL:" at 11400.38,3929.64 h60
  text "DRILLING:" at 11332.46,3790.64 h60
  text "REFERENCE:" at 11407.23,3673.64 h60
  text "X" at 12055.46,3673.64 h60
  text "AS SHOWN" at 12242.46,3673.64 h60
  text "X" at 12956.46,3673.64 h60
  text "NC_DRILL FILES" at 13093.46,3673.64 h60
  text "PTH MIN COPPER THICKNESS:" at 11407.23,3515.64 h60
  text "X" at 12757.46,3515.64 h60
  text "1MIL" at 12894.46,3515.64 h60
  text "OTHER" at 13391.46,3515.64 h60
  text "BOARD FINISH:" at 11332.46,3356.64 h60
  text "SILKSCREEN:" at 11487.68,3238.64 h60
  text "X" at 12436.46,3238.64 h60
  text "TOP" at 12562.46,3238.64 h60
  text "BOTTOM" at 13073.46,3238.64 h60
  text "SILKSCREEN COLOR:" at 11487.68,3071.64 h60
  text "X" at 12435.42,3071.64 h60
  text "WHITE" at 12562.46,3071.64 h60
  text "OTHER" at 13073.46,3071.64 h60
  text "SOLDER RESIST COLOR:" at 11487.68,2901.64 h60
  text "X" at 12055.42,2742.44 h60
  text "GREEN" at 12182.46,2742.44 h60
  text "BLUE" at 12773.46,2742.44 h60
  text "OTHER" at 13311.46,2742.44 h60
  text "IMMERSION GOLD (ENIG)" at 12393.46,2553.92 h60
  text "ENEPIG" at 13731,2550.64 h60
  text "SURFACE FINISH:" at 11332.46,2549.64 h60
  text "IMM. TIN/SILVER OR EQUIV" at 11662,2392.64 h60
  text "OTHER" at 13093.46,2392.64 h60
  text "X" at 11490,2390 h60
  text "ARRAY/PANEL:" at 11332.46,2213.64 h60
  text "CUT AND TRIM PER MECH LAYER 1" at 12393.46,2209.35 h60
  text "N.C. ROUTE" at 12393.46,2057.64 h60
  text "X" at 13072.46,2057.64 h60
  text "V. SCORE" at 13259.46,2057.64 h60
  text "CERTIFICATION:" at 11332.46,1920.64 h60
  text "MATERIALS AND WORKMANSHIP FOR ALL PCBS" at 12057.46,1920.64 h60
  text "TO MEET OR EXCEED THE REQUIREMENTS OF:" at 12057.46,1822.64 h60
  text "X" at 11683.96,1686.13 h60
  text "ANSI IPC-A-600F CLASS ->" at 11822.96,1686.13 h60
  text "X" at 13462.02,1686.13 h60
  text "2" at 13580.96,1686.14 h60
  text "1" at 13265.96,1684.64 h60
  text "3" at 13934.96,1684.64 h60
  text "X" at 11686.02,1526.64 h60
  text "UL 94V-0" at 11822.96,1526.64 h60
  text "X" at 12498.02,1526.64 h60
  text "RoHS" at 12634.96,1526.64 h60
  text "OTHER" at 13279.36,1526.64 h60
  text "PER ORDER" at 13676.42,1526.64 h60
  text "ADDITIONAL REQUIREMENTS:" at 11332.46,1385.64 h60
  text "MICROSECTION:" at 11407.23,1270.64 h60
  text "YES" at 12312.96,1270.64 h60
  text "REQUIRED" at 13174.46,1114.49 h60
  text "BARE BOARD ELEC. TEST:" at 11407.23,1111.64 h60
  text "NONE" at 12712.96,1111.64 h60
  text "PER ORDER" at 13766.46,1111.64 h60
  text "X" at 12590,1110 h60
  text "MANUFACTURER'S UL:" at 11407.23,954.64 h60
  text "RAIL" at 12572.96,950.35 h60
  text "METAL" at 13064.77,950.35 h60
  text "X" at 13440,950 h60
  text "SILK" at 13576.46,950.35 h60
  text ".Layer_Name" at 577,-858.49 h60
M11 Gerber Information:
  lines w10: -292,-930.17 6308,-930.17 ; -292,-726.83 6310,-726.83 ; -292,-523.5 -292,-1133.5 3713,-1133.5 6310,-1133.5 6310,-523.5 -291.5,-523.5 -291.5,-1133.5 1284,-1133.5 ; 2173,-1133.5 2173,-523.5 ; 3440,-726.83 3440,-523.5 ; 4280,-726.83 4280,-523.5 ; 4902,-1140 4902,-937.17
  text "ALL ARTWORK VIEWED FROM TOP SIDE" at -228.5,-655.67 h60
  text "BOARD #:" at 2248,-655.67 h60
  text ".PRJ_Number" at 2793.5,-655.67 h60
  text "REV:" at 3638,-655.67 h60
  text ".PCB_Rev" at 3929.5,-655.67 h60
  text "SVN REV:" at 4476,-655.67 h60
  text ".VersionControl_RevNumber" at 4982,-655.67 h60
  text "LAYER NAME =" at -228.5,-858.49 h60
  text "PLOT NAME =" at -228.5,-1064.34 h60
  text ".plot_File_Name" at 577,-1064.34 h60
  text "GENERATED    :" at 2250,-1064.34 h60
  text ".Print_Date" at 3119.5,-1064.34 h60
  text ".Print_Time" at 3848.5,-1064.34 h60
  text "TEXAS INSTRUMENTS" at 5113,-1064.34 h60
M12 Stackup:
  lines w6: 11330,7516.33 13810,7516.33 ; 11330,7624.83 13810,7624.83 ; 11270,7015 ccw(c11305,7015) 11305,6980 13835,6980 ccw(c13835,7015) 13870,7015 13870,7745 ccw(c13835,7745) 13835,7780 11305,7780 ccw(c11305,7745) 11270,7745 11270,7015
  text "Layer Stack Up Detail for: PMP9073.PcbDoc" at 11330,7658.22 h59
  text "Layer" at 11330,7584.33 h25
  text "Gerber" at 12203.47,7584.33 h25
  text "Copper" at 12737.92,7584.33 h25
  text "Dielectric" at 13313.19,7584.33 h25
  text "Name" at 11330,7534.33 h25
  text "Document" at 12203.47,7534.33 h25
  text "Thickness" at 12737.92,7534.33 h25
  text "Material" at 13313.19,7534.33 h25
  text "Top Solder Mask" at 11330,7438.33 h35
  text "(.GTS)" at 12203.47,7438.33 h35
  text "Solder Resist" at 13313.19,7438.33 h35
  text "Top Layer" at 11330,7338.33 h35
  text "(.GTL)" at 12203.47,7338.33 h35
  text "1.4mil" at 12737.92,7338.33 h35
  text "FR-4" at 13313.19,7288.33 h35
  text "Bottom Layer" at 11330,7238.33 h35
  text "(.GBL)" at 12203.47,7238.33 h35
  text "1.4mil" at 12737.92,7238.33 h35
  text "Bottom Solder Mask" at 11330,7138.33 h35
  text "(.GBS)" at 12203.47,7138.33 h35
  text "Solder Resist" at 13313.19,7138.33 h35
  text ".Layer_Name" at 577,-858.49 h60
M13 Component Bodies Top:
  text ".Layer_Name" at 577,-858.49 h60
M14 Component Bodies Bottom:
  text ".Layer_Name" at 577,-858.49 h60
M15 Courtyards Top:
  text ".Layer_Name" at 577,-858.49 h60
M16 Courtyards Bottom:
  text ".Layer_Name" at 577,-858.49 h60
Drill Drawing:
  text ".legend" at 5122.5,725.5 h60
  text "Drill Table" at 5147.5,540.5 h60
  text ".Layer_Name" at 577,-858.49 h60

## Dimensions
2100,210 to 2100,1260 on M2 Board Dimensions
0,0 to 2100,0 on M2 Board Dimensions
0,0 to 0,1500 on M2 Board Dimensions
